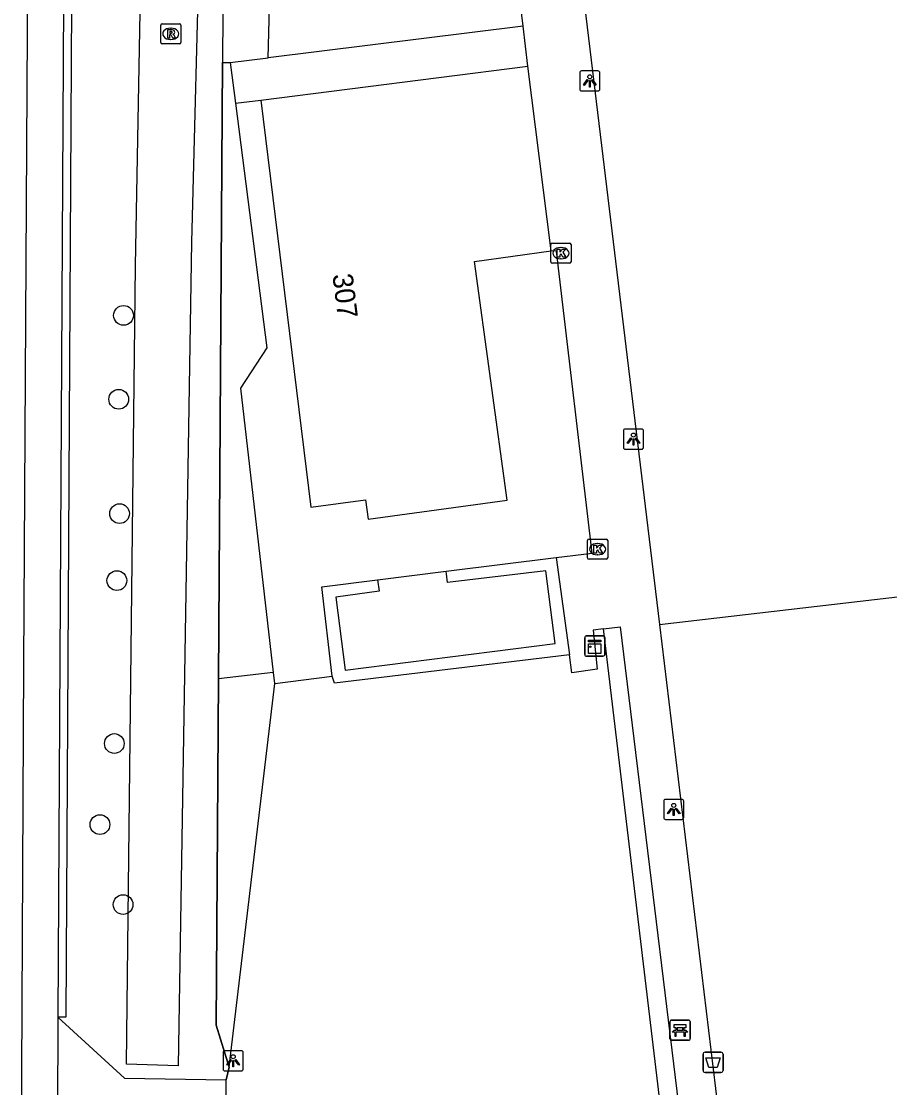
# Model space of a CAD drawing. Extents: x 162157 to 163165, y 378998 to 380775.
# Drawn here: x 162163.2 to 162206.2, y 380033.7 to 380086.5 of the extents above; entities that cross this region are included whole.
import ezdxf

# ---------------------------------------------------------------- set-up
doc = ezdxf.new("R2010")
doc.units = 0
for name, color, linetype in [('IMGEO_Afvalbak', 7, 'Continuous'), ('IMGEO_Bank', 7, 'Continuous'), ('IMGEO_Berm_open', 7, 'Continuous'), ('IMGEO_Boom', 7, 'Continuous'), ('IMGEO_Groenvoorziening', 7, 'Continuous'), ('IMGEO_Hek', 7, 'Continuous'), ('IMGEO_Kast', 7, 'Continuous'), ('IMGEO_Kolk', 7, 'Continuous'), ('IMGEO_Lichtpunt', 7, 'Continuous'), ('IMGEO_Pand', 7, 'Continuous'), ('IMGEO_Pand_nummerreeks', 7, 'Continuous'), ('IMGEO_Parkeervlak_gesloten', 7, 'Continuous'), ('IMGEO_Rijbaan_lokaal_gesloten', 7, 'Continuous'), ('IMGEO_Rijbaan_lokaal_open', 7, 'Continuous'), ('IMGEO_Rioolput', 7, 'Continuous'), ('IMGEO_Terreindeel_halfverhard', 7, 'Continuous'), ('IMGEO_Voetpad_halfverhard', 7, 'Continuous'), ('IMGEO_Voetpad_open', 7, 'Continuous'), ('IMGEO_Waterloop', 7, 'Continuous')]:
    doc.layers.add(name, color=color, linetype=linetype)

msp = doc.modelspace()

# ---------------------------------------------------------------- linework, layer by layer
at = {"layer": 'IMGEO_Afvalbak'}
for p, q in [((162197.088, 380035.421), (162197.878, 380035.421)), ((162197.878, 380035.421), (162197.088, 380035.421)), ((162196.988, 380034.521), (162196.988, 380035.321)), ((162196.988, 380035.321), (162196.988, 380034.521)), ((162197.978, 380035.321), (162197.978, 380034.521)), ((162197.978, 380034.521), (162197.978, 380035.321)), ((162197.878, 380034.421), (162197.088, 380034.421)), ((162197.088, 380034.421), (162197.878, 380034.421))]:
    msp.add_line(p, q, dxfattribs=at)
msp.add_lwpolyline([(162197.131, 380035.135), (162197.835, 380035.135), (162197.686, 380034.665), (162197.28, 380034.665), (162197.131, 380035.135)], dxfattribs=at)
for centre, start, end in [((162197.088, 380035.321), 90, 180), ((162197.088, 380035.321), 90, 180), ((162197.878, 380035.321), 0, 90), ((162197.878, 380035.321), 360, 90), ((162197.088, 380034.521), 180, 270), ((162197.088, 380034.521), 180, 270), ((162197.878, 380034.521), 270, 0), ((162197.878, 380034.521), 270, 0)]:
    msp.add_arc(centre, 0.1, start, end, dxfattribs=at)
at = {"layer": 'IMGEO_Bank'}
for p, q in [((162195.422, 380037.014), (162196.263, 380037.014)), ((162196.263, 380037.014), (162195.422, 380037.014)), ((162195.347, 380036.089), (162195.347, 380036.93)), ((162195.347, 380036.93), (162195.347, 380036.089)), ((162195.656, 380036.52), (162195.656, 380036.626)), ((162195.7, 380036.626), (162195.7, 380036.52)), ((162195.988, 380036.632), (162195.706, 380036.632)), ((162195.706, 380036.514), (162195.988, 380036.514)), ((162195.994, 380036.52), (162195.994, 380036.626)), ((162196.038, 380036.626), (162196.038, 380036.52)), ((162196.347, 380036.939), (162196.347, 380036.098)), ((162196.347, 380036.098), (162196.347, 380036.939)), ((162196.272, 380036.014), (162195.431, 380036.014)), ((162195.431, 380036.014), (162196.272, 380036.014)), ((162196.044, 380036.412), (162195.651, 380036.412))]:
    msp.add_line(p, q, dxfattribs=at)
for points in [[(162195.594, 380036.412), (162195.452, 380036.412), (162195.564, 380036.514), (162195.65, 380036.514)], [(162195.65, 380036.632), (162195.564, 380036.632), (162195.564, 380036.793), (162196.127, 380036.793), (162196.127, 380036.632), (162196.044, 380036.632)], [(162196.044, 380036.514), (162196.127, 380036.514), (162196.239, 380036.412), (162196.1, 380036.412)], [(162195.644, 380036.405), (162195.644, 380036.198), (162195.601, 380036.198), (162195.601, 380036.405)], [(162196.094, 380036.405), (162196.094, 380036.198), (162196.05, 380036.198), (162196.05, 380036.405)]]:
    msp.add_lwpolyline(points, dxfattribs=at)
for centre, radius, start, end in [((162195.425, 380036.936), 0.0779, 92.4484, 184.2845), ((162195.425, 380036.936), 0.0779, 92.4484, 184.2845), ((162196.269, 380036.936), 0.0779, 2.4484, 94.2845), ((162196.269, 380036.936), 0.0779, 2.4484, 94.2845), ((162195.649, 380036.625), 0.00671, 2.8957, 87.1043), ((162195.649, 380036.521), 0.00671, 272.8957, 357.1043), ((162195.706, 380036.625), 0.00671, 92.8957, 177.1043), ((162195.706, 380036.521), 0.00671, 182.8957, 267.1043), ((162195.988, 380036.625), 0.00671, 2.8957, 87.1043), ((162195.988, 380036.521), 0.00671, 272.8957, 357.1043), ((162196.045, 380036.625), 0.00671, 92.8957, 177.1043), ((162196.045, 380036.521), 0.00671, 182.8957, 267.1043), ((162195.425, 380036.092), 0.0779, 182.4484, 274.2845), ((162195.425, 380036.092), 0.0779, 182.4484, 274.2845), ((162195.594, 380036.405), 0.00671, 2.8957, 87.1043), ((162195.651, 380036.405), 0.00671, 92.8957, 177.1043), ((162196.043, 380036.405), 0.00671, 2.8957, 87.1043), ((162196.1, 380036.405), 0.00671, 92.8957, 177.1043), ((162196.269, 380036.092), 0.0779, 272.4484, 4.2845), ((162196.269, 380036.092), 0.0779, 272.4484, 4.2845)]:
    msp.add_arc(centre, radius, start, end, dxfattribs=at)
at = {"layer": 'IMGEO_Berm_open'}
msp.add_lwpolyline([(162165.486, 380125.971), (162165.864, 380125.971), (162165.869, 380122.903), (162165.398, 380037.16), (162164.999, 380037.164)], dxfattribs=at)
at = {"layer": 'IMGEO_Boom'}
for centre in [(162168.252, 380071.95), (162168.016, 380067.792), (162168.055, 380062.121), (162167.922, 380058.802), (162167.797, 380050.724), (162167.083, 380046.704), (162168.231, 380042.741)]:
    msp.add_circle(centre, 0.489, dxfattribs=at)
at = {"layer": 'IMGEO_Groenvoorziening'}
for points in [[(162175.426, 380084.724), (162176.15, 380112.24), (162176.146, 380112.277)], [(162173.347, 380112.055), (162173.166, 380084.491)], [(162172.964, 380053.937), (162173.166, 380084.491)], [(162173.166, 380084.491), (162173.547, 380084.491)], [(162173.483, 380034.68), (162172.851, 380036.76), (162172.964, 380053.937)], [(162175.675, 380054.248), (162172.964, 380053.937)]]:
    msp.add_lwpolyline(points, dxfattribs=at)
at = {"layer": 'IMGEO_Hek'}
for points in [[(162173.347, 380112.055), (162173.166, 380084.491)], [(162173.166, 380084.491), (162172.964, 380053.937)], [(162194.822, 380056.632), (162228.937, 380060.599)], [(162172.964, 380053.937), (162172.851, 380036.76), (162173.483, 380034.68)], [(162173.483, 380034.68), (162173.34, 380034.054)]]:
    msp.add_lwpolyline(points, dxfattribs=at)
at = {"layer": 'IMGEO_Kast'}
for p, q in [((162191.194, 380056.056), (162192.035, 380056.056)), ((162192.035, 380056.056), (162191.194, 380056.056)), ((162191.119, 380055.131), (162191.119, 380055.972)), ((162191.119, 380055.972), (162191.119, 380055.131)), ((162192.119, 380055.981), (162192.119, 380055.14)), ((162192.119, 380055.14), (162192.119, 380055.981)), ((162192.044, 380055.056), (162191.203, 380055.056)), ((162191.203, 380055.056), (162192.044, 380055.056))]:
    msp.add_line(p, q, dxfattribs=at)
for points in [[(162191.314, 380055.846), (162191.914, 380055.846), (162191.914, 380055.761), (162191.314, 380055.761), (162191.314, 380055.846)], [(162191.314, 380055.671), (162191.914, 380055.671), (162191.914, 380055.182), (162191.314, 380055.182), (162191.314, 380055.671)]]:
    msp.add_lwpolyline(points, dxfattribs=at)
msp.add_circle((162191.398, 380055.52), 0.0377, dxfattribs=at)
for centre, start, end in [((162191.197, 380055.978), 92.4484, 184.2845), ((162191.197, 380055.978), 92.4484, 184.2845), ((162192.041, 380055.978), 2.4484, 94.2845), ((162192.041, 380055.978), 2.4484, 94.2845), ((162191.197, 380055.134), 182.4484, 274.2845), ((162191.197, 380055.134), 182.4484, 274.2845), ((162192.041, 380055.134), 272.4484, 4.2845), ((162192.041, 380055.134), 272.4484, 4.2845)]:
    msp.add_arc(centre, 0.0779, start, end, dxfattribs=at)
at = {"layer": 'IMGEO_Kolk'}
for p, q in [((162189.441, 380074.609), (162189.441, 380075.461)), ((162189.516, 380075.535), (162190.368, 380075.535)), ((162189.929, 380075.315), (162189.954, 380075.315)), ((162190.442, 380075.461), (162190.442, 380074.609)), ((162189.952, 380074.755), (162189.927, 380074.755)), ((162190.368, 380074.535), (162189.516, 380074.535)), ((162191.334, 380060.86), (162192.186, 380060.86)), ((162191.259, 380059.934), (162191.259, 380060.786)), ((162191.747, 380060.64), (162191.772, 380060.64)), ((162192.26, 380060.786), (162192.26, 380059.934)), ((162192.186, 380059.86), (162191.334, 380059.86)), ((162191.77, 380060.08), (162191.745, 380060.08))]:
    msp.add_line(p, q, dxfattribs=at)
for points in [[(162189.441, 380074.609), (162189.441, 380075.461)], [(162189.516, 380075.535), (162190.368, 380075.535)], [(162189.762, 380075.235), (162189.885, 380075.235), (162189.885, 380075.084), (162190.015, 380075.235), (162190.179, 380075.235), (162190.033, 380075.084), (162190.186, 380074.835), (162190.034, 380074.835), (162189.949, 380074.999), (162189.885, 380074.932), (162189.885, 380074.835), (162189.762, 380074.835), (162189.762, 380075.235)], [(162190.442, 380075.461), (162190.442, 380074.609)], [(162190.368, 380074.535), (162189.516, 380074.535)], [(162191.334, 380060.86), (162192.186, 380060.86)], [(162191.259, 380059.934), (162191.259, 380060.786)], [(162191.58, 380060.56), (162191.703, 380060.56), (162191.703, 380060.409), (162191.833, 380060.56), (162191.997, 380060.56), (162191.851, 380060.409), (162192.004, 380060.16), (162191.852, 380060.16), (162191.767, 380060.324), (162191.703, 380060.257), (162191.703, 380060.16), (162191.58, 380060.16), (162191.58, 380060.56)], [(162192.26, 380060.786), (162192.26, 380059.934)], [(162192.186, 380059.86), (162191.334, 380059.86)]]:
    msp.add_lwpolyline(points, dxfattribs=at)
for centre, start, end in [((162189.518, 380075.459), 91.552, 178.448), ((162189.518, 380075.459), 91.552, 178.448), ((162190.366, 380075.459), 1.552, 88.448), ((162190.366, 380075.459), 1.552, 88.448), ((162189.518, 380074.611), 181.552, 268.448), ((162189.518, 380074.611), 181.552, 268.448), ((162190.366, 380074.611), 271.552, 358.448), ((162190.366, 380074.611), 271.552, 358.448), ((162191.336, 380060.784), 91.552, 178.448), ((162191.336, 380060.784), 91.552, 178.448), ((162192.184, 380060.784), 1.552, 88.448), ((162192.184, 380060.784), 1.552, 88.448), ((162191.336, 380059.936), 181.552, 268.448), ((162191.336, 380059.936), 181.552, 268.448), ((162192.184, 380059.936), 271.552, 358.448), ((162192.184, 380059.936), 271.552, 358.448)]:
    msp.add_arc(centre, 0.0765, start, end, dxfattribs=at)
for centre, major_axis, ratio, start_param, end_param in [((162189.928, 380075.035), (-0.387, 0.002), 0.722429, 4.712389, 7.853982), ((162189.953, 380075.035), (-0.39, 0.002), 0.717154, 1.570796, 4.712389), ((162191.746, 380060.36), (-0.387, 0.002), 0.722429, 4.712389, 7.853982), ((162191.771, 380060.36), (-0.39, 0.002), 0.717154, 1.570796, 4.712389)]:
    msp.add_ellipse(centre, major_axis=major_axis, ratio=ratio, start_param=start_param, end_param=end_param, dxfattribs=at)
at = {"layer": 'IMGEO_Lichtpunt'}
for p, q in [((162191.777, 380084.075), (162190.969, 380084.075)), ((162191.777, 380084.075), (162190.969, 380084.075)), ((162190.875, 380083.98), (162190.875, 380083.173)), ((162190.875, 380083.98), (162190.875, 380083.173)), ((162191.871, 380083.173), (162191.871, 380083.98)), ((162191.871, 380083.173), (162191.871, 380083.98)), ((162190.969, 380083.079), (162191.777, 380083.079)), ((162190.969, 380083.079), (162191.777, 380083.079)), ((162193.04, 380066.219), (162193.04, 380065.412)), ((162193.04, 380066.219), (162193.04, 380065.412)), ((162193.942, 380066.314), (162193.134, 380066.314)), ((162193.942, 380066.314), (162193.134, 380066.314)), ((162194.036, 380065.412), (162194.036, 380066.219)), ((162194.036, 380065.412), (162194.036, 380066.219)), ((162193.134, 380065.318), (162193.942, 380065.318)), ((162193.134, 380065.318), (162193.942, 380065.318)), ((162195.037, 380047.86), (162195.037, 380047.053)), ((162195.037, 380047.86), (162195.037, 380047.053)), ((162195.939, 380047.955), (162195.131, 380047.955)), ((162195.939, 380047.955), (162195.131, 380047.955)), ((162196.033, 380047.053), (162196.033, 380047.86)), ((162196.033, 380047.053), (162196.033, 380047.86)), ((162195.131, 380046.959), (162195.939, 380046.959)), ((162195.131, 380046.959), (162195.939, 380046.959)), ((162174.092, 380035.492), (162173.284, 380035.492)), ((162174.092, 380035.492), (162173.284, 380035.492)), ((162173.19, 380035.397), (162173.19, 380034.59)), ((162173.19, 380035.397), (162173.19, 380034.59)), ((162174.186, 380034.59), (162174.186, 380035.397)), ((162174.186, 380034.59), (162174.186, 380035.397)), ((162173.284, 380034.496), (162174.092, 380034.496)), ((162173.284, 380034.496), (162174.092, 380034.496))]:
    msp.add_line(p, q, dxfattribs=at)
for points in [[(162191.249, 380083.644), (162191.288, 380083.616), (162191.1, 380083.354), (162191.062, 380083.381), (162191.249, 380083.644)], [(162191.351, 380083.596), (162191.398, 380083.596), (162191.398, 380083.274), (162191.351, 380083.274), (162191.351, 380083.596)], [(162191.461, 380083.616), (162191.499, 380083.643), (162191.686, 380083.381), (162191.647, 380083.353), (162191.461, 380083.616)], [(162193.414, 380065.883), (162193.453, 380065.855), (162193.265, 380065.593), (162193.227, 380065.62), (162193.414, 380065.883)], [(162193.516, 380065.835), (162193.563, 380065.835), (162193.563, 380065.513), (162193.516, 380065.513), (162193.516, 380065.835)], [(162193.626, 380065.855), (162193.664, 380065.882), (162193.851, 380065.62), (162193.812, 380065.592), (162193.626, 380065.855)], [(162195.411, 380047.524), (162195.45, 380047.496), (162195.262, 380047.234), (162195.224, 380047.261), (162195.411, 380047.524)], [(162195.513, 380047.476), (162195.56, 380047.476), (162195.56, 380047.154), (162195.513, 380047.154), (162195.513, 380047.476)], [(162195.623, 380047.496), (162195.661, 380047.523), (162195.848, 380047.261), (162195.809, 380047.233), (162195.623, 380047.496)], [(162173.564, 380035.061), (162173.603, 380035.033), (162173.415, 380034.771), (162173.377, 380034.798), (162173.564, 380035.061)], [(162173.666, 380035.013), (162173.713, 380035.013), (162173.713, 380034.691), (162173.666, 380034.691), (162173.666, 380035.013)], [(162173.776, 380035.033), (162173.814, 380035.06), (162174.001, 380034.798), (162173.962, 380034.77), (162173.776, 380035.033)]]:
    msp.add_lwpolyline(points, dxfattribs=at)
for centre in [(162191.374, 380083.778), (162193.539, 380066.017), (162195.536, 380047.658), (162173.689, 380035.195)]:
    msp.add_circle(centre, 0.0994, dxfattribs=at)
for centre, start, end in [((162190.969, 380083.98), 90, 180), ((162190.969, 380083.98), 90, 180), ((162191.777, 380083.98), 0, 90), ((162191.777, 380083.98), 0, 90), ((162190.969, 380083.173), 180, 270), ((162190.969, 380083.173), 180, 270), ((162191.777, 380083.173), 270, 0), ((162191.777, 380083.173), 270, 360), ((162193.134, 380066.219), 90, 180), ((162193.134, 380066.219), 90, 180), ((162193.942, 380066.219), 0, 90), ((162193.942, 380066.219), 0, 90), ((162193.134, 380065.412), 180, 270), ((162193.134, 380065.412), 180, 270), ((162193.942, 380065.412), 270, 0), ((162193.942, 380065.412), 270, 360), ((162195.131, 380047.86), 90, 180), ((162195.131, 380047.86), 90, 180), ((162195.939, 380047.86), 0, 90), ((162195.939, 380047.86), 0, 90), ((162195.131, 380047.053), 180, 270), ((162195.131, 380047.053), 180, 270), ((162195.939, 380047.053), 270, 0), ((162195.939, 380047.053), 270, 360), ((162173.284, 380035.397), 90, 180), ((162173.284, 380035.397), 90, 180), ((162174.092, 380035.397), 0, 90), ((162174.092, 380035.397), 0, 90), ((162173.284, 380034.59), 180, 270), ((162173.284, 380034.59), 180, 270), ((162174.092, 380034.59), 270, 0), ((162174.092, 380034.59), 270, 360)]:
    msp.add_arc(centre, 0.0946, start, end, dxfattribs=at)
at = {"layer": 'IMGEO_Pand'}
for points in [[(162175.064, 380082.628), (162188.303, 380084.312)], [(162189.457, 380075.151), (162188.303, 380084.312)], [(162175.064, 380082.628), (162177.542, 380062.436), (162180.256, 380062.809), (162180.389, 380061.848), (162187.274, 380062.794), (162185.648, 380074.627), (162189.457, 380075.151)]]:
    msp.add_lwpolyline(points, dxfattribs=at)
at = {"layer": 'IMGEO_Parkeervlak_gesloten'}
for points in [[(162195.887, 380024.305), (162192.047, 380056.41)], [(162190.361, 380055.115), (162178.714, 380053.711), (162178.59, 380054.063)], [(162173.483, 380034.68), (162175.748, 380053.703)], [(162173.34, 380034.054), (162173.483, 380034.68)]]:
    msp.add_lwpolyline(points, dxfattribs=at)
at = {"layer": 'IMGEO_Rijbaan_lokaal_gesloten'}
for points in [[(162163.185, 380027.629), (162163.305, 380054.64), (162163.727, 380125.983)], [(162165.486, 380125.971), (162164.999, 380037.164)], [(162164.999, 380037.164), (162164.965, 380027.627)]]:
    msp.add_lwpolyline(points, dxfattribs=at)
at = {"layer": 'IMGEO_Rijbaan_lokaal_open'}
for points in [[(162164.999, 380037.164), (162168.308, 380034.127), (162173.34, 380034.054)], [(162173.295, 380028.997), (162173.34, 380034.054)]]:
    msp.add_lwpolyline(points, dxfattribs=at)
at = {"layer": 'IMGEO_Rioolput'}
for p, q in [((162170.095, 380085.485), (162170.095, 380086.337)), ((162170.17, 380086.411), (162171.022, 380086.411)), ((162170.583, 380086.191), (162170.608, 380086.191)), ((162171.096, 380086.337), (162171.096, 380085.485)), ((162171.022, 380085.411), (162170.17, 380085.411)), ((162170.606, 380085.631), (162170.581, 380085.631))]:
    msp.add_line(p, q, dxfattribs=at)
for points in [[(162170.095, 380085.485), (162170.095, 380086.337)], [(162170.17, 380086.411), (162171.022, 380086.411)], [(162171.096, 380086.337), (162171.096, 380085.485)], [(162170.684, 380086.109), (162170.432, 380086.111), (162170.432, 380085.711)], [(162170.432, 380085.711), (162170.556, 380085.711), (162170.556, 380085.873), (162170.567, 380085.873)], [(162170.61, 380086.03), (162170.556, 380086.03), (162170.556, 380085.949)], [(162170.556, 380085.949), (162170.608, 380085.949)], [(162170.614, 380085.844), (162170.685, 380085.711), (162170.825, 380085.711), (162170.76, 380085.837)], [(162171.022, 380085.411), (162170.17, 380085.411)]]:
    msp.add_lwpolyline(points, dxfattribs=at)
for centre, radius, start, end in [((162170.172, 380086.335), 0.0765, 91.552, 178.448), ((162170.172, 380086.335), 0.0765, 91.552, 178.448), ((162171.02, 380086.335), 0.0765, 1.552, 88.448), ((162171.02, 380086.335), 0.0765, 1.552, 88.448), ((162170.566, 380085.82), 0.0533, 26.0293, 88.6989), ((162170.592, 380086.138), 0.19, 274.7715, 282.9687), ((162170.616, 380085.934), 0.0964, 77.0061, 93.1865), ((162170.63, 380085.991), 0.0378, 276.6634, 79.6772), ((162170.683, 380085.999), 0.109, 350.3612, 89.416), ((162170.681, 380085.999), 0.112, 277.5842, 350.9817), ((162170.665, 380085.784), 0.108, 29.5134, 73.7905), ((162170.172, 380085.487), 0.0765, 181.552, 268.448), ((162170.172, 380085.487), 0.0765, 181.552, 268.448), ((162171.02, 380085.487), 0.0765, 271.552, 358.448), ((162171.02, 380085.487), 0.0765, 271.552, 358.448)]:
    msp.add_arc(centre, radius, start, end, dxfattribs=at)
for centre, major_axis, ratio, start_param, end_param in [((162170.582, 380085.911), (-0.387, 0.002), 0.722429, 4.712389, 7.853982), ((162170.607, 380085.911), (-0.39, 0.002), 0.717154, 1.570796, 4.712389)]:
    msp.add_ellipse(centre, major_axis=major_axis, ratio=ratio, start_param=start_param, end_param=end_param, dxfattribs=at)
at = {"layer": 'IMGEO_Terreindeel_halfverhard'}
msp.add_lwpolyline([(162194.822, 380056.632), (162228.937, 380060.599)], dxfattribs=at)
at = {"layer": 'IMGEO_Voetpad_halfverhard'}
msp.add_lwpolyline([(162180.852, 380058.838), (162180.928, 380058.279), (162178.787, 380057.988), (162179.235, 380054.366), (162189.649, 380055.678), (162189.19, 380059.283), (162184.325, 380058.71), (162184.25, 380059.262)], dxfattribs=at)
at = {"layer": 'IMGEO_Voetpad_open'}
for points in [[(162190.413, 380093.089), (162194.822, 380056.632)], [(162188.063, 380086.289), (162187.478, 380091.097)], [(162188.063, 380086.289), (162175.426, 380084.724)], [(162188.303, 380084.312), (162188.063, 380086.289)], [(162173.547, 380084.491), (162175.426, 380084.724)], [(162173.547, 380084.491), (162173.807, 380082.466)], [(162173.807, 380082.466), (162175.064, 380082.628)], [(162173.807, 380082.466), (162175.366, 380070.343), (162174.056, 380068.346), (162175.675, 380054.248)], [(162189.701, 380059.943), (162191.492, 380060.166), (162189.718, 380075.138), (162189.457, 380075.151)], [(162194.822, 380056.632), (162199.226, 380020.209), (162233.359, 380024.296), (162228.937, 380060.599)], [(162184.25, 380059.262), (162189.701, 380059.943)], [(162189.701, 380059.943), (162190.361, 380055.115)], [(162180.852, 380058.838), (162184.25, 380059.262)], [(162178.59, 380054.063), (162178.084, 380058.488), (162180.852, 380058.838)], [(162192.047, 380056.41), (162191.538, 380056.351), (162191.737, 380054.409), (162190.483, 380054.224), (162190.361, 380055.115)], [(162192.047, 380056.41), (162192.874, 380056.505), (162196.797, 380024.421), (162195.887, 380024.305)], [(162175.675, 380054.248), (162175.738, 380053.702), (162175.748, 380053.703)], [(162175.748, 380053.703), (162178.59, 380054.063)]]:
    msp.add_lwpolyline(points, dxfattribs=at)
at = {"layer": 'IMGEO_Waterloop'}
msp.add_lwpolyline([(162172.984, 380134.992), (162172.447, 380107.456), (162171.631, 380075.578), (162170.967, 380034.746), (162168.408, 380034.827), (162168.85, 380074.41), (162169.945, 380133.695)], dxfattribs=at)

# ---------------------------------------------------------------- texts
at = {"layer": 'IMGEO_Pand_nummerreeks'}
msp.add_text('307', height=1, rotation=277.1229, dxfattribs=at).set_placement((162178.609, 380073.966))

doc.saveas('drawing.dxf')
